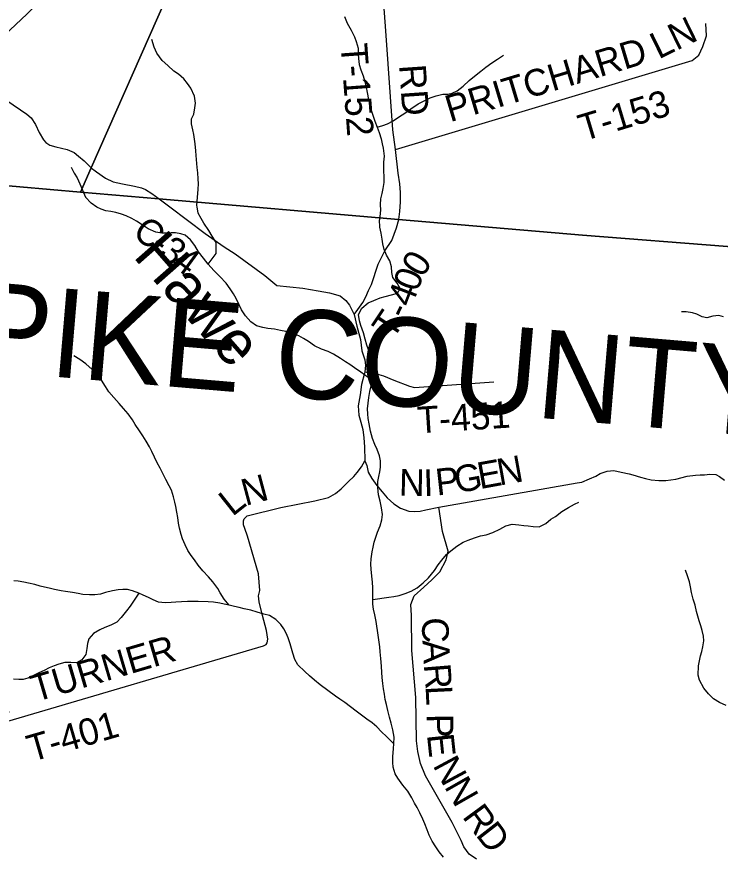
# Model space of a CAD drawing. Extents: x 0 to 34, y 0 to 22.
# Drawn here: x 5.019 to 6.52, y 17.795 to 19.582 of the extents above; entities that cross this region are included whole.
import ezdxf

# ---------------------------------------------------------------- set-up
doc = ezdxf.new("R2010")
doc.units = 0
for name, color, linetype in [('Default', 7, 'Continuous'), ('GM_X_County_Road', 7, 'Continuous'), ('GM_X_County_Road_Text', 7, 'Continuous'), ('GM_X_County_Text', 7, 'Continuous'), ('GM_X_Minor_River', 7, 'Continuous'), ('GM_X_Minor_River_Text', 7, 'Continuous'), ('GM_X_State_Route', 7, 'Continuous'), ('GM_X_Township_Road', 7, 'Continuous'), ('GM_X_Township_Road_Text', 7, 'Continuous'), ('SH_Cut_Line', 7, 'Continuous')]:
    doc.layers.add(name, color=color, linetype=linetype)

msp = doc.modelspace()

# ---------------------------------------------------------------- linework, layer by layer
at = {"layer": 'Default'}
for points in [[(5.8621, 20.8), (2.8183, 20.8), (3.0244, 19.9995), (3.1893, 19.3592), (4.7641, 19.2419), (4.831, 19.2363), (5.1554, 19.2083), (5.1782, 19.2598), (5.5496, 20.1004), (5.5679, 20.1313), (5.5783, 20.1528), (5.5834, 20.1771), (5.5869, 20.1933), (5.5951, 20.2127), (5.6047, 20.2229), (5.6166, 20.2359)], [(9, 18.8941), (9, 20.8), (5.8621, 20.8), (5.6166, 20.2359), (5.6047, 20.2229), (5.5951, 20.2127), (5.5869, 20.1933), (5.5834, 20.1771), (5.5783, 20.1528), (5.5679, 20.1313), (5.5496, 20.1004), (5.1782, 19.2598), (5.1554, 19.2083), (5.3224, 19.1939), (5.8337, 19.1499), (6.226, 19.1161), (6.8442, 19.0679), (8.0305, 18.9725), (8.8762, 18.9027)]]:
    msp.add_lwpolyline(points, close=True, dxfattribs=at)
msp.add_lwpolyline([(9, 14), (9, 18.8941), (8.8762, 18.9027), (8.0305, 18.9725), (6.8442, 19.0679), (6.226, 19.1161), (5.8337, 19.1499), (5.3224, 19.1939), (5.1554, 19.2083), (4.831, 19.2363), (4.7661, 18.9124), (5.0018, 18.1008), (4.9996, 18.0806), (4.937, 17.4953), (4.9239, 17.3511), (4.9207, 17.3435), (4.6758, 16.8903), (4.7194, 16.7424)], dxfattribs=at)
at = {"layer": 'GM_X_County_Road'}
for points in [[(4.9164, 19.4541), (4.9979, 19.4035), (5.041, 19.3741), (5.05, 19.3665), (5.0594, 19.3519), (5.067, 19.3348), (5.076, 19.3196), (5.0812, 19.3138), (5.0898, 19.3083), (5.1026, 19.3049), (5.1266, 19.2989), (5.1414, 19.2924), (5.1511, 19.2846), (5.1627, 19.2744), (5.1784, 19.2593), (5.1867, 19.2531), (5.1893, 19.2513)], [(5.1893, 19.2513), (5.2084, 19.2379), (5.2246, 19.23), (5.2449, 19.2259), (5.2703, 19.2208), (5.2851, 19.2175), (5.2939, 19.2137), (5.3072, 19.2051), (5.3226, 19.1934)], [(5.3226, 19.1934), (5.3455, 19.1767), (5.4211, 19.1197), (5.4616, 19.0917), (5.4847, 19.0763), (5.5485, 19.0301), (5.5739, 19.009), (5.6294, 19.0034), (5.6622, 18.9977), (5.686, 18.9937), (5.709, 18.9873), (5.7214, 18.9773), (5.7289, 18.9674), (5.7388, 18.9471), (5.7446, 18.922), (5.7526, 18.8942), (5.7554, 18.8699), (5.7616, 18.8509), (5.7634, 18.8387), (5.7614, 18.825), (5.7609, 18.822), (5.7546, 18.7982), (5.7514, 18.7758), (5.7477, 18.7524), (5.7486, 18.7326), (5.753, 18.7174), (5.7574, 18.7018), (5.7595, 18.6843), (5.7608, 18.6653), (5.7616, 18.6353), (5.766, 18.6254), (5.7689, 18.6113), (5.7767, 18.5979), (5.7871, 18.583), (5.7983, 18.5689), (5.8095, 18.5566), (5.8234, 18.5439), (5.838, 18.5343), (5.8554, 18.528), (5.8675, 18.5275), (5.88, 18.5283), (5.892, 18.5309), (5.9194, 18.5364), (6.2143, 18.5885), (6.2247, 18.5899), (6.2406, 18.5967), (6.2547, 18.6027), (6.2634, 18.608), (6.2786, 18.6129), (6.2931, 18.6144), (6.3086, 18.6113), (6.3257, 18.6078), (6.3336, 18.6055), (6.3496, 18.6002), (6.3606, 18.5979), (6.3727, 18.5944), (6.389, 18.5936), (6.4034, 18.5936), (6.4247, 18.5962), (6.4494, 18.6025), (6.4668, 18.6044), (6.4767, 18.6055), (6.4862, 18.6055), (6.4976, 18.6066), (6.5101, 18.6058), (6.5184, 18.6019), (6.529, 18.5943)], [(5.9998, 17.7862), (5.9844, 17.797), (5.9728, 17.8123), (5.9669, 17.826), (5.9477, 17.8646), (5.8912, 17.9635), (5.8802, 17.9902), (5.8744, 18.0154), (5.8716, 18.0385), (5.8707, 18.1308), (5.862, 18.2311), (5.8609, 18.3055), (5.8596, 18.3287), (5.867, 18.3476), (5.8873, 18.3663), (5.9048, 18.3817), (5.9217, 18.3986), (5.9352, 18.4242), (5.9391, 18.4424), (5.9275, 18.4847), (5.9194, 18.5364)]]:
    msp.add_lwpolyline(points, dxfattribs=at)
at = {"layer": 'GM_X_Minor_River'}
for points in [[(5.7183, 19.5821), (5.7238, 19.5683), (5.7324, 19.5534), (5.7394, 19.5389), (5.743, 19.529), (5.7474, 19.5146), (5.7476, 19.502), (5.7479, 19.4926), (5.7497, 19.48), (5.7529, 19.4686), (5.7584, 19.456), (5.7617, 19.4442), (5.7642, 19.4321), (5.7664, 19.4207), (5.7696, 19.4058), (5.7725, 19.3948), (5.7761, 19.3807), (5.783, 19.359), (5.7882, 19.3464), (5.7922, 19.3354), (5.7962, 19.3213), (5.7987, 19.311), (5.8005, 19.3015), (5.8026, 19.2844), (5.8017, 19.2716), (5.8011, 19.2534), (5.8021, 19.2408), (5.8019, 19.2287), (5.8003, 19.2158), (5.7979, 19.2052), (5.7947, 19.1935), (5.7942, 19.1814), (5.7952, 19.1696)], [(5.4034, 19.1792), (5.4062, 19.214), (5.4067, 19.2258), (5.4061, 19.2364), (5.4055, 19.2493), (5.4041, 19.2607), (5.4022, 19.2858), (5.4011, 19.296), (5.3998, 19.3108), (5.3984, 19.3207), (5.397, 19.331), (5.3949, 19.3409), (5.392, 19.3538), (5.3921, 19.3644), (5.3968, 19.3742), (5.3988, 19.3878), (5.4001, 19.3977), (5.398, 19.4125), (5.3902, 19.4297), (5.3835, 19.4396), (5.3753, 19.4496), (5.3641, 19.4596), (5.3543, 19.4661), (5.3412, 19.4777), (5.3293, 19.4884), (5.3177, 19.5041), (5.3122, 19.5171), (5.3075, 19.5331)], [(5.7882, 19.3464), (5.8003, 19.3501), (5.8102, 19.3534), (5.822, 19.3597), (5.8353, 19.369), (5.8468, 19.3765), (5.8597, 19.3858), (5.8753, 19.3959), (5.8871, 19.4018), (5.9012, 19.4088), (5.9137, 19.4132), (5.9278, 19.4165), (5.9384, 19.4171), (5.9478, 19.4189), (5.9585, 19.4237), (5.9715, 19.4342), (5.9845, 19.4461), (5.9955, 19.4555), (6.0089, 19.4656), (6.0199, 19.4742), (6.0322, 19.4839), (6.0447, 19.4917), (6.0577, 19.5003)], [(5.1353, 19.2612), (5.1419, 19.2483), (5.1479, 19.2383), (5.1534, 19.2257), (5.1655, 19.1975)], [(5.7763, 18.8074), (5.7532, 18.8245), (5.7399, 18.8332), (5.7297, 18.8408), (5.7202, 18.8465), (5.71, 18.8537), (5.6948, 18.8629), (5.6835, 18.8682), (5.6694, 18.8735), (5.6546, 18.8807), (5.6414, 18.8898), (5.6311, 18.8959), (5.6205, 18.9016), (5.6069, 18.9073), (5.5928, 18.9111), (5.5818, 18.9134), (5.5686, 18.9161), (5.5549, 18.9176), (5.5439, 18.9195), (5.5302, 18.9233), (5.5185, 18.9313), (5.5071, 18.9442), (5.4988, 18.9571), (5.4935, 18.9678), (5.4874, 18.9815), (5.4817, 18.9913), (5.4741, 19.0016), (5.4658, 19.0138), (5.4522, 19.0282), (5.4393, 19.0411), (5.4275, 19.0544), (5.4173, 19.0674), (5.4071, 19.0807), (5.3991, 19.094), (5.39, 19.1065), (5.3786, 19.116), (5.3688, 19.1194), (5.3581, 19.121), (5.3487, 19.121), (5.3384, 19.1206), (5.3289, 19.1206), (5.3157, 19.1225), (5.2997, 19.1301), (5.2868, 19.1385), (5.2743, 19.1461), (5.2645, 19.1518), (5.2523, 19.1575), (5.2425, 19.1613), (5.2307, 19.1643), (5.2197, 19.1666), (5.2095, 19.1685), (5.1992, 19.1715), (5.1898, 19.1757), (5.1776, 19.1845), (5.1655, 19.1975)], [(5.4275, 19.0544), (5.4442, 19.0772), (5.4442, 19.1008), (5.4363, 19.1141), (5.4287, 19.1263), (5.4181, 19.1422), (5.4128, 19.1517), (5.4063, 19.1635), (5.4037, 19.1764), (5.4034, 19.1792)], [(5.7952, 19.1696), (5.7926, 19.1492)], [(5.7533, 18.9237), (5.7502, 18.9335), (5.7483, 18.9472), (5.7552, 18.9609), (5.7688, 18.9723), (5.7806, 18.9769), (5.7946, 18.9826), (5.8053, 18.9856), (5.8182, 18.989), (5.8314, 18.9924), (5.8371, 19.0027), (5.8303, 19.0137), (5.8216, 19.0263), (5.8189, 19.0369), (5.8186, 19.0487), (5.8148, 19.0616), (5.808, 19.0738), (5.8026, 19.0859), (5.8, 19.0981), (5.7985, 19.1076), (5.7966, 19.1205), (5.7939, 19.1331), (5.7926, 19.1492)], [(6.5265, 18.9421), (6.5166, 18.9451), (6.5037, 18.9438), (6.4912, 18.9403), (6.4813, 18.9421), (6.4699, 18.9477), (6.4604, 18.951), (6.4471, 18.9531), (6.4368, 18.9527)], [(5.9294, 17.7901), (5.9203, 17.8019), (5.9131, 17.8122), (5.9052, 17.8247), (5.8991, 17.8372), (5.8946, 17.849), (5.8897, 17.8612), (5.8855, 17.8715), (5.8791, 17.8852), (5.8734, 17.8962), (5.8677, 17.9057), (5.8616, 17.9167), (5.8533, 17.9308), (5.8427, 17.9441), (5.8317, 17.9589), (5.8264, 17.9684), (5.8222, 17.9821), (5.8215, 17.992), (5.8215, 18.0045), (5.8226, 18.0224), (5.8238, 18.0323), (5.8241, 18.046), (5.8215, 18.0616), (5.8181, 18.0764), (5.8139, 18.0885), (5.8105, 18.103), (5.8075, 18.1155), (5.8052, 18.1266), (5.8033, 18.1376), (5.8014, 18.149), (5.7999, 18.1604), (5.7988, 18.1733), (5.798, 18.184), (5.7969, 18.1977), (5.7958, 18.214), (5.7946, 18.2281), (5.7935, 18.2391), (5.792, 18.249), (5.7901, 18.2638), (5.786, 18.2931), (5.7829, 18.3071), (5.7799, 18.3193), (5.7788, 18.3299), (5.7784, 18.3398), (5.7784, 18.3645), (5.7777, 18.3767), (5.7765, 18.3892), (5.7754, 18.4041), (5.7746, 18.4147), (5.775, 18.4261), (5.7773, 18.4413), (5.7792, 18.4512), (5.7815, 18.4618), (5.7849, 18.4725), (5.7887, 18.4831), (5.7944, 18.4968), (5.7982, 18.5097), (5.7993, 18.5211), (5.7975, 18.5348), (5.7941, 18.5493), (5.7906, 18.563), (5.7895, 18.5782), (5.7895, 18.5911), (5.7918, 18.6017), (5.7937, 18.6116), (5.7948, 18.6215), (5.7949, 18.6352), (5.793, 18.6458), (5.788, 18.6591), (5.7831, 18.6698), (5.7778, 18.6831), (5.774, 18.6983), (5.7706, 18.7142), (5.7691, 18.7253), (5.768, 18.7351), (5.7676, 18.7462), (5.7684, 18.7583), (5.7703, 18.7705), (5.7725, 18.783), (5.7748, 18.7948), (5.7763, 18.8074), (5.7764, 18.8313), (5.7752, 18.8457), (5.7741, 18.8556), (5.7711, 18.8685), (5.7658, 18.8818), (5.7624, 18.8944), (5.7586, 18.9081), (5.7533, 18.9237)], [(5.4723, 18.3277), (5.4613, 18.3406), (5.4534, 18.3536), (5.4481, 18.3631), (5.4374, 18.3775), (5.4283, 18.3882), (5.4162, 18.4011), (5.4064, 18.4129), (5.398, 18.4243), (5.3912, 18.4338), (5.384, 18.444), (5.3783, 18.4562), (5.3726, 18.4687), (5.37, 18.4782), (5.3662, 18.4916), (5.3643, 18.5022), (5.3624, 18.5147), (5.3609, 18.5261), (5.3582, 18.5379), (5.356, 18.5474), (5.3533, 18.5585), (5.3495, 18.5725), (5.3446, 18.582), (5.3374, 18.5957), (5.3306, 18.6082), (5.3253, 18.6197), (5.3188, 18.6311), (5.3132, 18.6432), (5.3075, 18.655), (5.3022, 18.6653), (5.295, 18.677), (5.2878, 18.6888), (5.281, 18.6995), (5.2719, 18.7128), (5.2658, 18.7223), (5.2571, 18.7352), (5.2465, 18.747), (5.2377, 18.7573), (5.226, 18.7702), (5.2158, 18.7823), (5.2086, 18.7934), (5.1998, 18.807), (5.1911, 18.8177), (5.1801, 18.8299), (5.1665, 18.842), (5.1536, 18.8511), (5.1407, 18.8591)], [(5.7784, 18.3398), (5.8129, 18.3448), (5.8232, 18.3463), (5.8349, 18.3482), (5.8478, 18.3524), (5.8603, 18.3577), (5.8736, 18.3645), (5.8861, 18.3752), (5.8975, 18.3858), (5.91, 18.4014), (5.918, 18.4136), (5.926, 18.4234), (5.9358, 18.4356), (5.9453, 18.4436), (5.9582, 18.4531), (5.9711, 18.4618), (5.9821, 18.466), (5.9958, 18.4709), (6.0087, 18.4751), (6.0201, 18.4774), (6.0345, 18.4827), (6.0493, 18.4899), (6.0626, 18.4968), (6.0758, 18.5002), (6.0899, 18.4991), (6.1009, 18.4975), (6.1103, 18.4968), (6.1206, 18.4956), (6.1335, 18.4945), (6.1475, 18.5017), (6.1585, 18.5112), (6.168, 18.5169), (6.1817, 18.5275), (6.1961, 18.5359), (6.2086, 18.5428), (6.2181, 18.5473)], [(6.5323, 18.114), (6.5185, 18.12), (6.5052, 18.1278), (6.4945, 18.1383), (6.4845, 18.1504), (6.4756, 18.1674), (6.4728, 18.1784), (6.4734, 18.1981), (6.4752, 18.2088), (6.4778, 18.2194), (6.4808, 18.2289), (6.4829, 18.2388), (6.4851, 18.2514), (6.4843, 18.2616), (6.4815, 18.2733), (6.4784, 18.2836), (6.4749, 18.2942), (6.4717, 18.304), (6.4694, 18.3142), (6.4662, 18.3275), (6.4623, 18.3403), (6.4588, 18.3547), (6.4564, 18.3669), (6.4544, 18.3775), (6.4501, 18.3903), (6.4454, 18.4021)], [(5.8238, 18.0323), (5.8082, 18.0479), (5.7972, 18.0578), (5.7874, 18.0684), (5.7771, 18.0768), (5.7661, 18.0848), (5.7544, 18.0931), (5.743, 18.1019), (5.7312, 18.111), (5.7187, 18.1201), (5.7085, 18.127), (5.699, 18.1334), (5.6827, 18.1456), (5.6664, 18.1581), (5.6543, 18.1676), (5.6433, 18.1771), (5.6334, 18.1859), (5.619, 18.2007), (5.6126, 18.2117), (5.608, 18.2254), (5.6027, 18.2452), (5.5982, 18.2581), (5.5936, 18.2676), (5.5887, 18.2771), (5.5823, 18.2866), (5.572, 18.2973), (5.5584, 18.3053), (5.5463, 18.3087), (5.5322, 18.3129), (5.5186, 18.3167), (5.5045, 18.3197), (5.4939, 18.3224), (5.4833, 18.3247), (5.4723, 18.3277), (5.4617, 18.33), (5.4522, 18.3315), (5.4389, 18.3338), (5.4272, 18.3346), (5.4059, 18.3353), (5.3836, 18.3353), (5.3707, 18.3346), (5.3585, 18.3342), (5.3487, 18.3334), (5.3358, 18.3323), (5.3217, 18.3338), (5.31, 18.3388), (5.3005, 18.3437), (5.2891, 18.3486), (5.2793, 18.3532), (5.2664, 18.3581), (5.2554, 18.3608), (5.2451, 18.3608), (5.2357, 18.36), (5.2231, 18.3578), (5.2087, 18.3543), (5.1981, 18.3513), (5.1856, 18.3494), (5.1742, 18.3494), (5.1602, 18.3502), (5.1503, 18.3521), (5.1382, 18.3544), (5.1234, 18.357), (5.1139, 18.3582), (5.0999, 18.3608), (5.0881, 18.3635), (5.0786, 18.3658), (5.0688, 18.3684), (5.0578, 18.3715), (5.0441, 18.3745), (5.0346, 18.3768), (5.0225, 18.3787), (5.013, 18.3798)], [(5.2793, 18.3532), (5.2614, 18.3258), (5.2531, 18.3152), (5.2421, 18.3011), (5.2326, 18.2916), (5.2201, 18.2852), (5.2068, 18.2802), (5.1965, 18.2753), (5.1829, 18.2673), (5.173, 18.2559), (5.17, 18.2456), (5.1688, 18.2354), (5.1666, 18.2221), (5.1578, 18.2107), (5.1464, 18.205), (5.1343, 18.2057), (5.1214, 18.2053), (5.1089, 18.2015), (5.099, 18.1981), (5.088, 18.1939), (5.0774, 18.1886), (5.066, 18.1833), (5.0531, 18.1772), (5.0425, 18.1719), (5.033, 18.1692), (5.0235, 18.1689), (5.0122, 18.1696)]]:
    msp.add_lwpolyline(points, dxfattribs=at)
at = {"layer": 'GM_X_State_Route'}
msp.add_lwpolyline([(4.7822, 19.2658), (4.8193, 19.3162), (4.8615, 19.3727), (4.9164, 19.4541), (4.9387, 19.4846), (4.9923, 19.5416), (5.0416, 19.5883), (5.0927, 19.6394)], dxfattribs=at)
at = {"layer": 'GM_X_Township_Road'}
for points in [[(5.8339, 19.1494), (5.8361, 19.1664), (5.8376, 19.1875), (5.8379, 19.2071), (5.8362, 19.2256), (5.8324, 19.2487), (5.8274, 19.2989), (5.8212, 19.3409), (5.8062, 19.5516), (5.7955, 19.6967), (5.7938, 19.7146), (5.7919, 19.7268), (5.7874, 19.7395), (5.6668, 19.9679), (5.628, 20.0558), (5.6168, 20.0847), (5.6048, 20.1295), (5.6, 20.1652), (5.5953, 20.2121), (5.5904, 20.2509)], [(5.8274, 19.2989), (6.4598, 19.4887), (6.4741, 19.4997), (6.4825, 19.5188), (6.4905, 19.5411), (6.4891, 19.5678)], [(5.7388, 18.9471), (5.7465, 18.9581), (5.7573, 18.9731), (5.7638, 18.9848), (5.7697, 18.9984), (5.7755, 19.0112), (5.7901, 19.0546), (5.8042, 19.083), (5.8189, 19.1048), (5.8294, 19.1322), (5.8339, 19.1494)], [(5.7614, 18.825), (5.7918, 18.8192), (5.8012, 18.8162), (5.8237, 18.8073), (5.8571, 18.7944), (5.8676, 18.7914), (6.0369, 18.8033)], [(4.9999, 18.0801), (5.5456, 18.2407), (5.5509, 18.2437), (5.5536, 18.2471), (5.5544, 18.2554), (5.5516, 18.2737), (5.5436, 18.3053), (5.536, 18.335), (5.535, 18.3475), (5.5374, 18.3585), (5.5351, 18.3942), (5.511, 18.4749), (5.5059, 18.4909), (5.5026, 18.4989), (5.5027, 18.5077), (5.5042, 18.5118), (5.5104, 18.5182), (5.5828, 18.5356), (5.6552, 18.55), (5.6844, 18.5572), (5.6992, 18.5658), (5.711, 18.5755), (5.7267, 18.5909), (5.7385, 18.6018), (5.7454, 18.6104), (5.7546, 18.6225), (5.7616, 18.6353)]]:
    msp.add_lwpolyline(points, dxfattribs=at)
at = {"layer": 'SH_Cut_Line'}
for points in [[(9, 18.8941), (9, 20.8), (2.2, 20.8), (2.2, 19.4329), (2.7961, 19.3885), (3.1893, 19.3592), (4.7641, 19.2419), (4.831, 19.2363), (5.1554, 19.2083), (5.3224, 19.1939), (5.8337, 19.1499), (6.226, 19.1161), (6.8442, 19.0679), (8.0305, 18.9725), (8.8762, 18.9027)], [(2.2, 19.4329), (2.2, 14), (9, 14), (9, 18.8941), (8.8762, 18.9027), (8.0305, 18.9725), (6.8442, 19.0679), (6.226, 19.1161), (5.8337, 19.1499), (5.3224, 19.1939), (5.1554, 19.2083), (4.831, 19.2363), (4.7641, 19.2419), (3.1893, 19.3592), (2.7961, 19.3885)]]:
    msp.add_lwpolyline(points, close=True, dxfattribs=at)

# ---------------------------------------------------------------- texts
at = {"layer": 'GM_X_County_Road_Text'}
for s, rotation, p in [('C', 322.6758, (5.2633, 19.1161)), ('3', 322.8993, (5.3192, 19.0735)), ('-', 322.7089, (5.3005, 19.0877)), ('4', 323.9308, (5.348, 19.0517)), ('N', 10.2203, (6.0488, 18.5823)), ('G', 10.1033, (5.9576, 18.566)), ('E', 10.2168, (6.007, 18.5748)), ('N', 358.7249, (5.834, 18.5611)), ('I', 2.119, (5.8876, 18.56)), ('P', 6.3504, (5.9155, 18.5612)), ('C', 271.5457, (5.8831, 18.3009)), ('A', 273.2294, (5.8844, 18.2524)), ('R', 274.6455, (5.8873, 18.201)), ('L', 272.8211, (5.8911, 18.1549)), ('P', 270.5844, (5.8934, 18.0956)), ('E', 276.0702, (5.8941, 18.0513)), ('N', 298.2605, (5.9057, 17.9862)), ('N', 299.6184, (5.9301, 17.9409)), ('R', 306.3239, (5.9681, 17.8766)), ('D', 307.8849, (5.9967, 17.8376))]:
    msp.add_text(s, height=0.0568, rotation=rotation, dxfattribs=at).set_placement(p)
at = {"layer": 'GM_X_County_Text'}
msp.add_text('PIKE COUNTY', height=0.189394, rotation=355.1489, dxfattribs=at).set_placement((4.9178, 18.83))
at = {"layer": 'GM_X_Minor_River_Text'}
msp.add_text('Hawe', height=0.09469, rotation=311.2867, dxfattribs=at).set_placement((5.2652, 19.071))
at = {"layer": 'GM_X_Township_Road_Text'}
for s, height, rotation, p in [('LN', 0.05682, 26.0859, (6.3884, 19.4906)), ('T-152', 0.05682, 274.2052, (5.7099, 19.5233)), ('PRITCHARD', 0.05682, 16.7457, (5.9434, 19.3569)), ('RD', 0.05682, 273.9449, (5.8347, 19.4787)), ('T-153', 0.05682, 16.7529, (6.2275, 19.3161)), ('0', 0.0568, 57.8964, (5.8846, 19.0236)), ('0', 0.0568, 69.5266, (5.8737, 18.9935)), ('4', 0.0568, 69.1573, (5.8611, 18.9604)), ('-', 0.0568, 64.5537, (5.8491, 18.9348)), ('T', 0.0568, 56.0567, (5.8208, 18.8916)), ('T-451', 0.05682, 3.6464, (5.8753, 18.6936)), ('N', 0.0568, 15.0196, (5.507, 18.539)), ('L', 0.0568, 38.4001, (5.4791, 18.5153)), ('TURNER', 0.05682, 16.419, (5.0594, 18.121)), ('T-401', 0.05682, 16.2151, (5.0508, 17.9932))]:
    msp.add_text(s, height=height, rotation=rotation, dxfattribs=at).set_placement(p)

doc.saveas('drawing.dxf')
